// Mitsubishi GX Works2 project: L系列PLC与BD4523通信例程   PLC: L02

PROGRAM MAIN
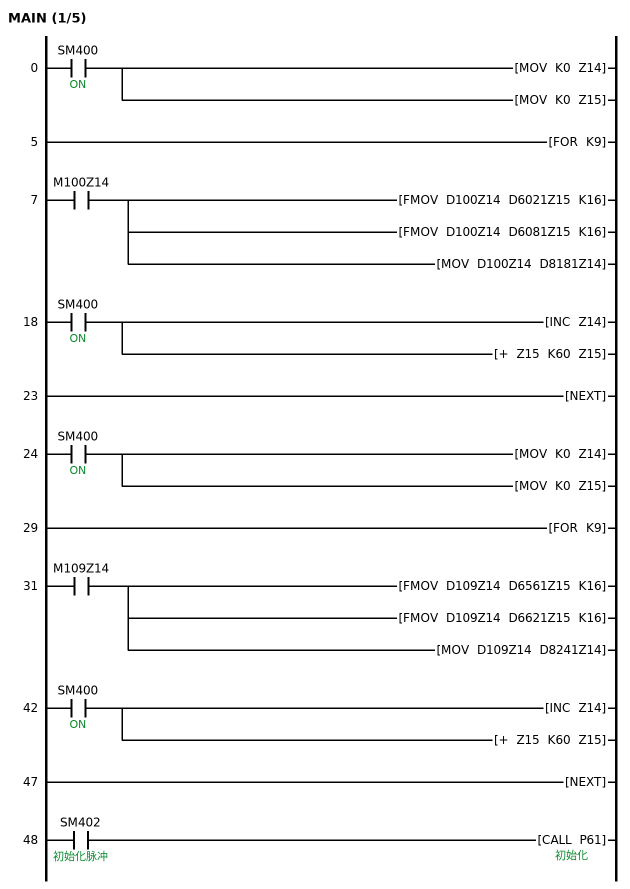
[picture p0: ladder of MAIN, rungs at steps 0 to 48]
0     LD      SM400  ; ON
      MOV     K0 Z14
      MOV     K0 Z15
5     FOR     K9
7     LD      M100Z14
      FMOV    D100Z14 D6021Z15 K16
      FMOV    D100Z14 D6081Z15 K16
      MOV     D100Z14 D8181Z14
18    LD      SM400  ; ON
      INC     Z14
      +       Z15 K60 Z15
23    NEXT
24    LD      SM400  ; ON
      MOV     K0 Z14
      MOV     K0 Z15
29    FOR     K9
31    LD      M109Z14
      FMOV    D109Z14 D6561Z15 K16
      FMOV    D109Z14 D6621Z15 K16
      MOV     D109Z14 D8241Z14
42    LD      SM400  ; ON
      INC     Z14
      +       Z15 K60 Z15
47    NEXT
48    LD      SM402  ; 初始化脉冲
      CALL    P61  ; 初始化
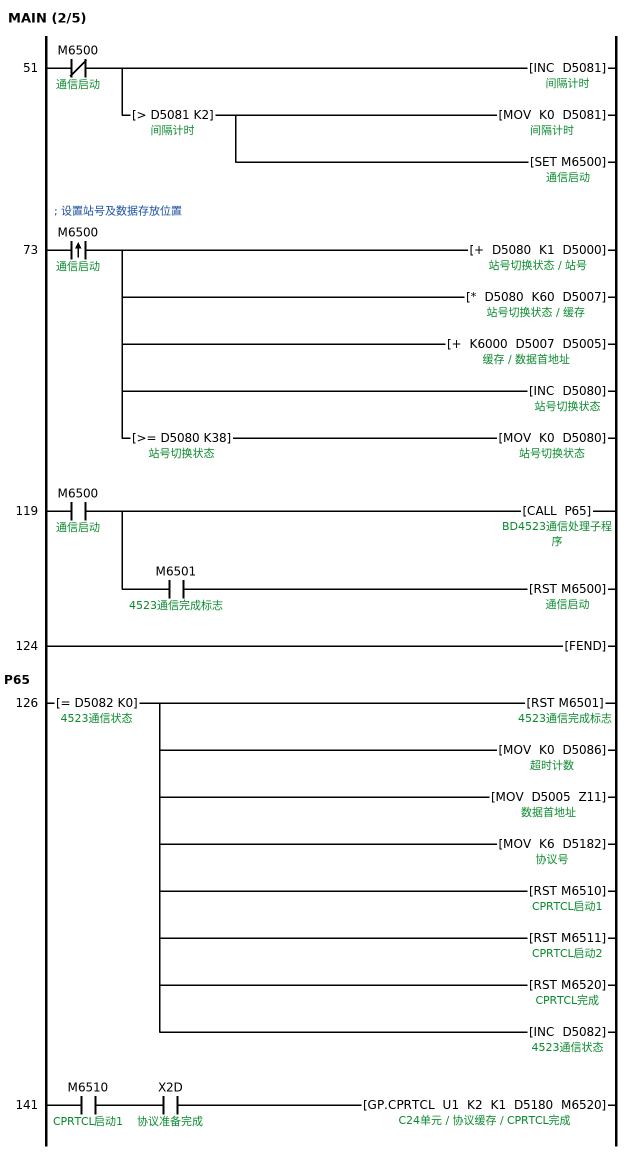
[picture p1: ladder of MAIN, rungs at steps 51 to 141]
51    LDI     M6500  ; 通信启动
      INC     D5081  ; 间隔计时
      AND>    D5081 K2  ; 间隔计时
      MOV     K0 D5081
      SET     M6500  ; 通信启动
; 设置站号及数据存放位置
73    LDP     M6500  ; 通信启动
      +       D5080 K1 D5000  ; 站号切换状态 / 站号
        [note] 参与通讯站号
      *       D5080 K60 D5007  ; 缓存
      +       K6000 D5007 D5005  ; 数据首地址
        [note] 数据开始位置（D号）
      INC     D5080
      AND>=   D5080 K38  ; 站号切换状态
      MOV     K0 D5080
        [note] BD4523模块个数
119   LD      M6500  ; 通信启动
      CALL    P65  ; BD4523通信处理子程序
      AND     M6501  ; 4523通信完成标志
      RST     M6500  ; 通信启动
124   FEND
      P65
126   LD=     D5082 K0  ; 4523通信状态
      RST     M6501  ; 4523通信完成标志
      MOV     K0 D5086  ; 超时计数
      MOV     D5005 Z11
      MOV     K6 D5182  ; 协议号
      RST     M6510  ; CPRTCL启动1
      RST     M6511  ; CPRTCL启动2
      RST     M6520  ; CPRTCL完成
      INC     D5082
141   LD      M6510  ; CPRTCL启动1
      AND     X2D  ; 协议准备完成
      GP.CPRTCL U1 K2 K1 D5180 M6520  ; C24单元 / 协议缓存
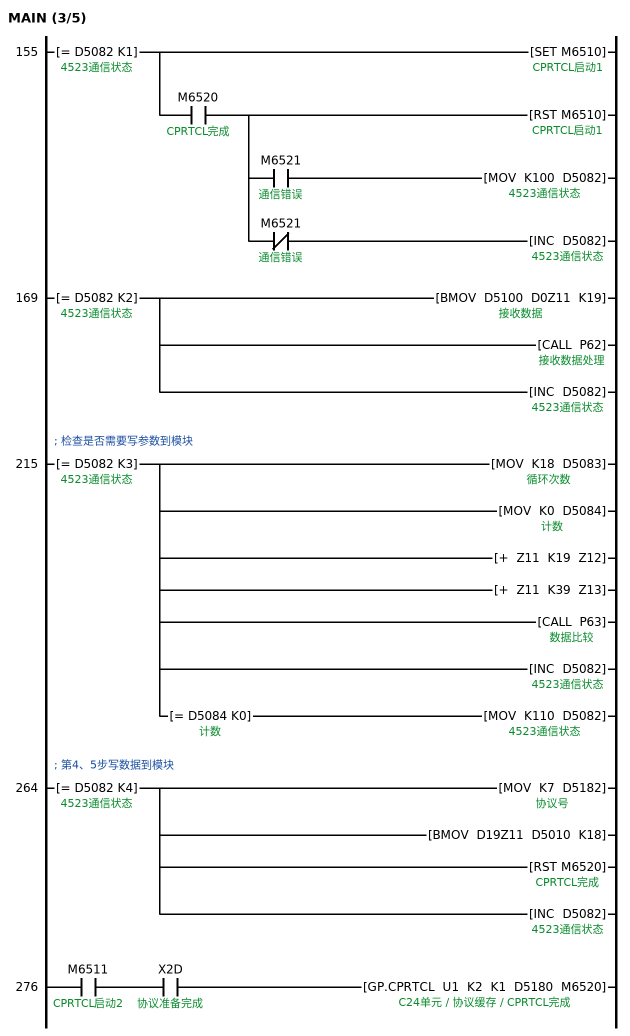
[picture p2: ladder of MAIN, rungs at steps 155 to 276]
155   LD=     D5082 K1  ; 4523通信状态
      SET     M6510  ; CPRTCL启动1
      AND     M6520  ; CPRTCL完成
      RST     M6510  ; CPRTCL启动1
      MPS
      AND     M6521  ; 通信错误
      MOV     K100 D5082
      MPP
      ANI     M6521  ; 通信错误
      INC     D5082
169   LD=     D5082 K2  ; 4523通信状态
      BMOV    D5100 D0Z11 K19  ; 接收数据
        [note] 数据处理
      CALL    P62  ; 接收数据处理
      INC     D5082
; 检查是否需要写参数到模块
215   LD=     D5082 K3  ; 4523通信状态
      MOV     K18 D5083  ; 循环次数
      MOV     K0 D5084  ; 计数
      +       Z11 K19 Z12
      +       Z11 K39 Z13
      CALL    P63  ; 数据比较
      INC     D5082
      AND=    D5084 K0  ; 计数
      MOV     K110 D5082
; 第4、5步写数据到模块
264   LD=     D5082 K4  ; 4523通信状态
      MOV     K7 D5182
      BMOV    D19Z11 D5010 K18
      RST     M6520  ; CPRTCL完成
      INC     D5082
276   LD      M6511  ; CPRTCL启动2
      AND     X2D  ; 协议准备完成
      GP.CPRTCL U1 K2 K1 D5180 M6520
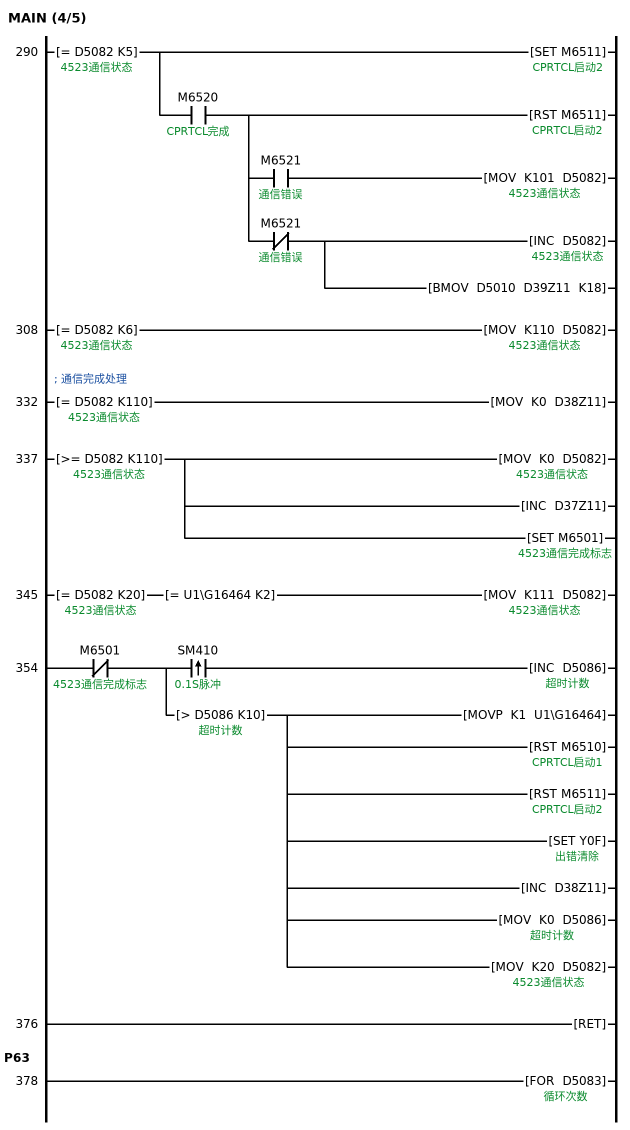
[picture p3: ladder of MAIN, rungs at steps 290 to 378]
290   LD=     D5082 K5  ; 4523通信状态
      SET     M6511  ; CPRTCL启动2
      AND     M6520  ; CPRTCL完成
      RST     M6511  ; CPRTCL启动2
      MPS
      AND     M6521  ; 通信错误
      MOV     K101 D5082
      MPP
      ANI     M6521  ; 通信错误
      INC     D5082
      BMOV    D5010 D39Z11 K18
308   LD=     D5082 K6  ; 4523通信状态
      MOV     K110 D5082
; 通信完成处理
332   LD=     D5082 K110  ; 4523通信状态
      MOV     K0 D38Z11
337   LD>=    D5082 K110  ; 4523通信状态
      MOV     K0 D5082
      INC     D37Z11
      SET     M6501  ; 4523通信完成标志
345   LD=     D5082 K20  ; 4523通信状态
      AND=    U1\G16464 K2
      MOV     K111 D5082
354   LDI     M6501  ; 4523通信完成标志
      MPS
      ANDP    SM410  ; 0.1S脉冲
      INC     D5086
      MPP
      AND>    D5086 K10  ; 超时计数
      MOVP    K1 U1\G16464
      RST     M6510  ; CPRTCL启动1
      RST     M6511  ; CPRTCL启动2
      SET     Y0F  ; 出错清除
      INC     D38Z11
      MOV     K0 D5086
      MOV     K20 D5082
376   RET
      P63
378   FOR     D5083
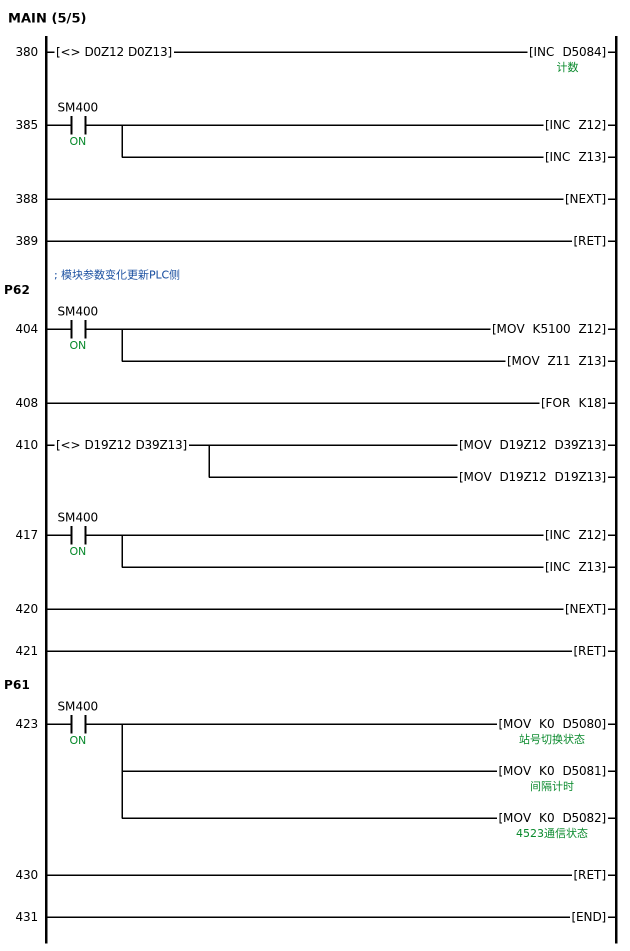
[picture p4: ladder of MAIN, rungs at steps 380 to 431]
380   LD<>    D0Z12 D0Z13
      INC     D5084
385   LD      SM400  ; ON
      INC     Z12
      INC     Z13
388   NEXT
389   RET
; 模块参数变化更新PLC侧
      P62
404   LD      SM400  ; ON
      MOV     K5100 Z12
      MOV     Z11 Z13
408   FOR     K18
410   LD<>    D19Z12 D39Z13
      MOV     D19Z12 D39Z13
      MOV     D19Z12 D19Z13
417   LD      SM400  ; ON
      INC     Z12
      INC     Z13
420   NEXT
421   RET
      P61
423   LD      SM400  ; ON
      MOV     K0 D5080
      MOV     K0 D5081
      MOV     K0 D5082
430   RET
431   END
END_PROGRAM

// device comments not shown above
D48  ; 通信故障计数
D100  ; 给定温度1
D101  ; 给定温度2
D102  ; 给定温度3
D103  ; 给定温度4
D104  ; 给定温度5
D105  ; 给定温度6
D106  ; 给定温度7
D107  ; 给定温度8
D108  ; 给定温度9
D109  ; 给定温度10
D110  ; 给定温度11
D111  ; 给定温度12
D112  ; 给定温度13
D113  ; 给定温度14
D114  ; 给定温度15
D115  ; 给定温度16
D116  ; 给定温度17
D117  ; 给定温度18
D5001  ; 地址
D5002  ; 数据
D5006  ; #1通道启/停M号
D5008  ; 缓存
D5085  ; 通道号
D6021  ; 1站SV1
D6081  ; 2站SV1
D6141  ; 3站SV1
D6201  ; 4站SV1
D6261  ; 5站SV1
D6321  ; 6站SV1
D6381  ; 7站SV1
D6441  ; 8站SV1
D6501  ; 9站SV1
D6561  ; 9站SV1
D6621  ; 10站SV1
D6681  ; 11站SV1
D6741  ; 12站SV1
D6801  ; 13站SV1
D6861  ; 14站SV1
D6921  ; 15站SV1
D6981  ; 16站SV1
M6512  ; CPRTCL启动3
